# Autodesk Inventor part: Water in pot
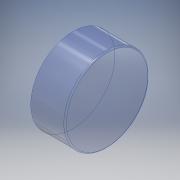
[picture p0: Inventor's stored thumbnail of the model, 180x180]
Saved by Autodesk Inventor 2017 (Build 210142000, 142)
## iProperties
Created: 2020-03
Part Number: Water in pot
Material: Water
Document SubType Name: Modeling
Designer: user
Density: 0.9983 g/cm^3
Appearance: Tropical Blue
Author: user
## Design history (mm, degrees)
sketch "Sketch1"
  geometry: L1 (3, 0)-(80, 0); L2 (80, 0)-(80, -98); L3 (0, -98)-(0, -3); L4 (80, -98)-(0, -98); A1 r 3 centre (3, -3) between (3, 0) and (0, -3); 1 further point
  constraints: 8 end point, 2 point on circle, 2 point on line, 2 tangent, 1 centre point, 1 horizontal, 1 perpendicular
  dimensions: "d0" = 80 distance of point (0, 0) L1.end; "d2" = 3 radius of A1; "d4" = 98 distance between parallel lines of L4 L1
revolve "Revolution1" sketch "Sketch1" stored, may be unused: angle "d3" = 90 deg
body "Solid1"
